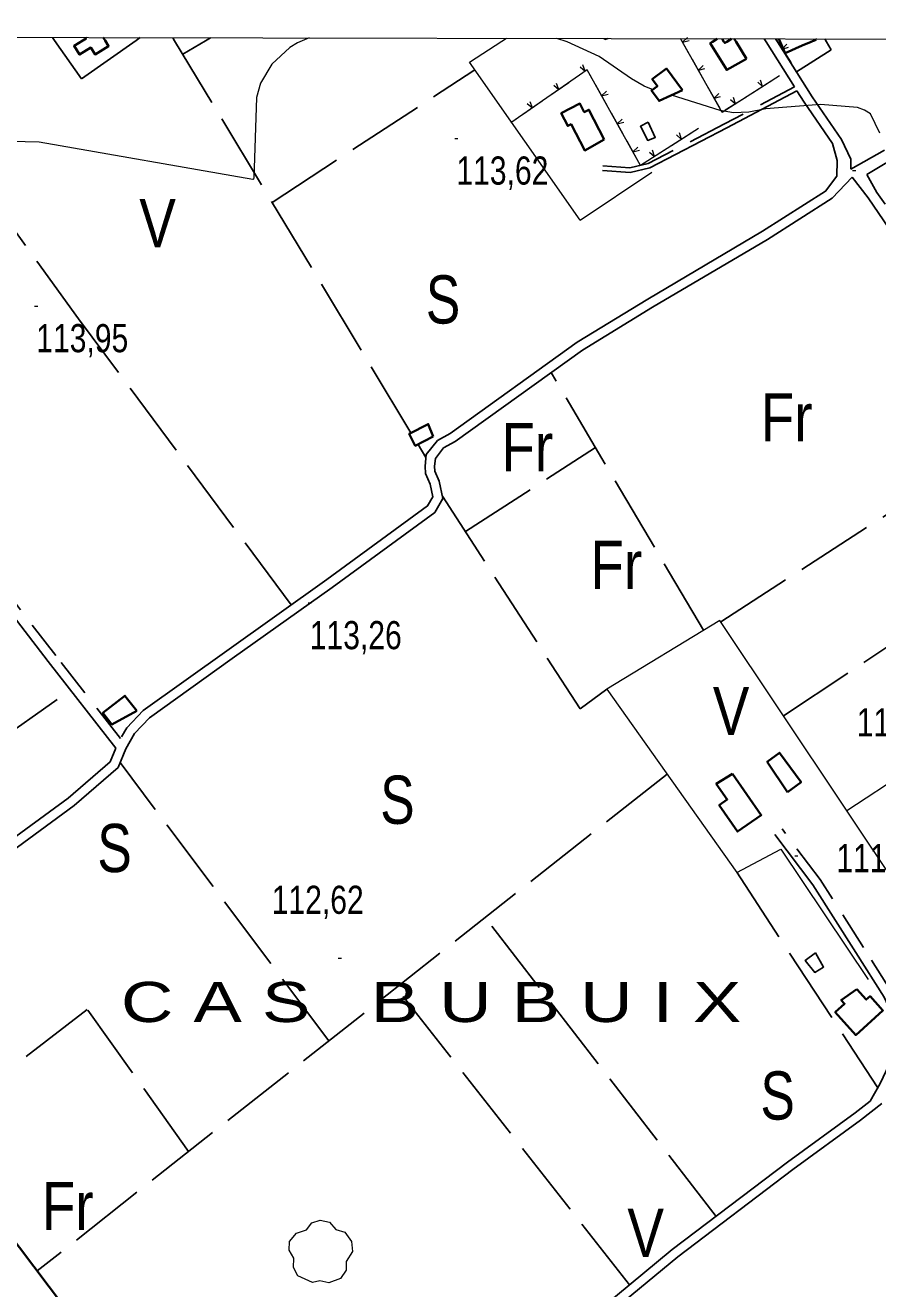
# Model space of a CAD drawing. Extents: x 483840 to 488445, y 4386047 to 4389027.
# Drawn here: x 486095.2 to 486360.3, y 4388367.4 to 4388760.3 of the extents above; entities that cross this region are included whole.
import ezdxf
from ezdxf.enums import TextEntityAlignment as Align

# ---------------------------------------------------------------- set-up
doc = ezdxf.new("R2010")
doc.units = 0
doc.header["$LTSCALE"] = 4
doc.linetypes.add('LONG_DASHED', pattern=[7.5, 6, -1.5])
doc.linetypes.add('MEDIUM_DASHED', pattern=[4.5, 3, -1.5])
for name, color, linetype, lineweight in [('1', 7, 'Continuous', 13), ('21', 7, 'Continuous', 25), ('24', 7, 'Continuous', 13), ('25', 7, 'LONG_DASHED', 25), ('29', 7, 'Continuous', 13), ('38', 7, 'Continuous', 25), ('47', 7, 'Continuous', 35), ('51', 7, 'Continuous', 13), ('6', 7, 'Continuous', 35), ('7', 7, 'Continuous', 13), ('9', 7, 'Continuous', 13)]:
    doc.layers.add(name, color=color, linetype=linetype, lineweight=lineweight)
doc.layers.add('31', color=7, linetype='Continuous')
doc.layers.add('5', color=7, linetype='Continuous')

msp = doc.modelspace()

# ---------------------------------------------------------------- linework, layer by layer
at = {"layer": '1'}
msp.add_lwpolyline([(484110.5, 4388760.3), (487685.8, 4388753.5), (487681.9, 4386441.2), (484105.5, 4386448.1)], close=True, dxfattribs=at)
at = {"layer": '21'}
for p, q in [((486275.39, 4388755.88), (486275.22, 4388756.18)), ((486276.32, 4388756.18), (486275.39, 4388755.88))]:
    msp.add_line(p, q, dxfattribs=at)
for points in [[(486288.93, 4388730.17), (486286.46, 4388728.89), (486288.79, 4388724.47), (486291.12, 4388725.45)], [(486340.97, 4388471.91), (486337.74, 4388469.5), (486340.68, 4388465.76), (486343.45, 4388467.41)]]:
    msp.add_lwpolyline(points, close=True, dxfattribs=at)
at = {"layer": '24'}
for p, q in [((486301.46, 4388751.78), (486299, 4388756.15)), ((486328.62, 4388756.09), (486333.35, 4388748.59)), ((486328.62, 4388756.09), (486332.62, 4388749.75)), ((486306.35, 4388743.08), (486302.68, 4388749.61)), ((486327.66, 4388743.22), (486321.32, 4388739.2)), ((486264.17, 4388742.44), (486258.01, 4388738.16)), ((486276.25, 4388735.11), (486272.59, 4388741.66)), ((486311.25, 4388734.37), (486307.58, 4388740.91)), ((486255.97, 4388736.74), (486249.81, 4388732.45)), ((486319.22, 4388737.86), (486312.89, 4388733.85)), ((486281.13, 4388726.39), (486277.47, 4388732.94)), ((486247.77, 4388731.03), (486246.23, 4388729.96)), ((486286, 4388717.67), (486282.34, 4388724.22)), ((486302.43, 4388726.85), (486296.11, 4388722.81)), ((486294.02, 4388721.47), (486287.7, 4388717.42))]:
    msp.add_line(p, q, dxfattribs=at)
for points in [[(486329.76, 4388744.55), (486311.9, 4388733.22), (486299, 4388756.15)], [(486301.1, 4388756.5), (486299.62, 4388755.05), (486301.62, 4388755.57)], [(486332.02, 4388754.44), (486330.62, 4388752.92), (486332.59, 4388753.54)], [(486267.71, 4388747.34), (486269.29, 4388746), (486268.59, 4388747.95)], [(486305.99, 4388747.8), (486304.52, 4388746.34), (486306.52, 4388746.86)], [(486304.53, 4388728.19), (486286.55, 4388716.69), (486269.92, 4388746.44), (486246.23, 4388729.96)], [(486271.38, 4388743.83), (486269.92, 4388746.44), (486266.21, 4388743.86)], [(486322.96, 4388742.61), (486324.49, 4388741.21), (486323.87, 4388743.18)], [(486259.51, 4388741.63), (486261.09, 4388740.3), (486260.38, 4388742.24)], [(486275.9, 4388739.83), (486274.42, 4388738.39), (486276.43, 4388738.9)], [(486310.89, 4388739.09), (486309.41, 4388737.64), (486311.42, 4388738.16)], [(486251.31, 4388735.93), (486252.89, 4388734.59), (486252.18, 4388736.54)], [(486314.53, 4388737.26), (486316.06, 4388735.86), (486315.43, 4388737.83)], [(486280.78, 4388731.11), (486279.3, 4388729.67), (486281.3, 4388730.18)], [(486297.74, 4388726.22), (486299.27, 4388724.83), (486298.64, 4388726.8)], [(486285.65, 4388722.39), (486284.17, 4388720.95), (486286.17, 4388721.46)], [(486289.32, 4388720.84), (486290.86, 4388719.45), (486290.23, 4388721.42)]]:
    msp.add_lwpolyline(points, dxfattribs=at)
at = {"layer": '25'}
for p, q in [((486104.3, 4388755.58), (486103.65, 4388756.51)), ((486130.94, 4388756.46), (486129.61, 4388755.53)), ((486141.59, 4388755.51), (486141.03, 4388756.44)), ((486215.13, 4388633.56), (486141.59, 4388755.51)), ((486151.24, 4388755.49), (486144.13, 4388751.31)), ((486152.8, 4388756.42), (486151.23, 4388755.49)), ((486343.86, 4388756.05), (486344.38, 4388755.11)), ((486171.92, 4388705.23), (486234.99, 4388746.46)), ((486063.66, 4388735.58), (486111.7, 4388669.05)), ((486177.83, 4388580.04), (486111.7, 4388669.05)), ((486306.1, 4388572.15), (486258.72, 4388652.3)), ((486311.46, 4388574.81), (486404.56, 4388634.97)), ((486219.77, 4388625.86), (486217.31, 4388629.94)), ((486232.03, 4388602.88), (486272.51, 4388628.99)), ((486330.99, 4388545.58), (486366.24, 4388568.94)), ((486011.75, 4388485.18), (486109.24, 4388553.5)), ((486189.6, 4388444.51), (486124.64, 4388531.01)), ((486294.77, 4388527.46), (486098.88, 4388372.95)), ((486316.44, 4388496.9), (486360.29, 4388429.87)), ((486310.02, 4388389.91), (486238.21, 4388482.85)), ((486283.12, 4388368.6), (486210.52, 4388461.01))]:
    msp.add_line(p, q, dxfattribs=at)
for points in [[(486129.62, 4388755.54), (486112.63, 4388743.69), (486104.29, 4388755.58)], [(486344.38, 4388755.12), (486345.76, 4388752.62), (486335.01, 4388745.77)], [(486224.92, 4388613.85), (486267.7, 4388547.78), (486276.02, 4388553.87)], [(486145.98, 4388410.1), (486114.45, 4388454.28), (486066.46, 4388417.1)]]:
    msp.add_lwpolyline(points, dxfattribs=at)
at = {"layer": '29'}
msp.add_lwpolyline([(486184.51, 4388369.3), (486179.97, 4388371.42), (486178.56, 4388373.96), (486178.66, 4388376.94), (486177.29, 4388379.35), (486177.33, 4388382.1), (486179.49, 4388384.7), (486182.68, 4388385.7), (486184.33, 4388387.89), (486186.9, 4388388.72), (486189.76, 4388388.07), (486191.71, 4388385.8), (486194.52, 4388384.98), (486196.65, 4388382.13), (486196.89, 4388379), (486195.01, 4388375.85), (486195.01, 4388373.17), (486193.19, 4388370.56), (486189.57, 4388369.22), (486186.8, 4388369.85)], close=True, dxfattribs=at)
at = {"layer": '38'}
for p, q in [((486325.59, 4388755.15), (486325, 4388756.09)), ((486334.4, 4388741.12), (486325.59, 4388755.16)), ((486329.11, 4388755.14), (486328.52, 4388756.08))]:
    msp.add_line(p, q, dxfattribs=at)
for points in [[(486351.95, 4388715.56), (486351.95, 4388718.62), (486349, 4388724.83), (486339.88, 4388738), (486329.11, 4388755.15)], [(486356.91, 4388713.91), (486390.65, 4388734.09), (486420.06, 4388754.97)], [(486125.14, 4388539.04), (486126.7, 4388541.81), (486131.81, 4388547.23), (486157.81, 4388565.81), (486188.91, 4388587.92), (486220.29, 4388610.84), (486221.92, 4388613.65), (486221.08, 4388617.59), (486219.65, 4388620.89), (486219.5, 4388623.24), (486219.87, 4388626.79), (486223.34, 4388631.17), (486227.31, 4388633.36), (486266.8, 4388661.78), (486288.77, 4388675.17), (486324.43, 4388696.23), (486344.05, 4388708.71), (486347.55, 4388713.33), (486347.69, 4388718.26), (486346.27, 4388723.56), (486337.4, 4388736.36), (486335.17, 4388739.91)], [(486335.17, 4388739.91), (486313.31, 4388728.36), (486289.38, 4388715.93), (486283.27, 4388714.48), (486274.69, 4388715.15)], [(486033.72, 4388459.48), (486052.43, 4388473.19), (486076.56, 4388492.95), (486110.38, 4388517.64), (486124.01, 4388529.51), (486126.45, 4388535.31), (486129.11, 4388540.04), (486133.77, 4388544.98), (486159.53, 4388563.39), (486190.65, 4388585.51), (486222.54, 4388608.81), (486225.06, 4388613.15), (486223.93, 4388618.5), (486222.58, 4388621.6), (486222.48, 4388623.18), (486222.74, 4388625.62), (486225.29, 4388628.86), (486228.9, 4388630.84), (486268.45, 4388659.3), (486290.29, 4388672.62), (486325.99, 4388693.7), (486346.1, 4388706.49), (486352.36, 4388713.1)], [(486438.94, 4388583.08), (486417.59, 4388614.59), (486380.14, 4388673.12), (486357.27, 4388706.61), (486352.36, 4388713.1)], [(486123.29, 4388535.46), (486102.27, 4388562.43), (486079.04, 4388592.63), (486059.8, 4388616.3), (486048.45, 4388632.26)], [(486031.88, 4388461.81), (486050.61, 4388475.53), (486074.74, 4388495.3), (486108.53, 4388519.96), (486121.54, 4388531.3), (486123.29, 4388535.46)], [(486368.72, 4388444.06), (486362.33, 4388458.05), (486353.45, 4388471.97), (486340.07, 4388493.03), (486328.26, 4388508.69)], [(486167.47, 4388276.64), (486196.77, 4388298.32), (486229.44, 4388324.85), (486265.99, 4388354.46), (486296.41, 4388379.57), (486332.22, 4388406.78), (486353.27, 4388422.12), (486357.92, 4388425.73), (486361.06, 4388431.21), (486363.9, 4388437.14), (486368.72, 4388444.06)], [(486169.13, 4388274.35), (486198.5, 4388296.09), (486231.22, 4388322.66), (486267.77, 4388352.28), (486298.16, 4388377.36), (486333.9, 4388404.52), (486354.96, 4388419.87), (486361.55, 4388424.99)]]:
    msp.add_lwpolyline(points, dxfattribs=at)
at = {"layer": '38', "linetype": 'MEDIUM_DASHED'}
for points in [[(486351.95, 4388715.56), (486389.06, 4388736.53), (486415.05, 4388754.98)], [(486334.4, 4388741.12), (486312.65, 4388729.62), (486288.88, 4388717.27), (486283.16, 4388715.92), (486274.8, 4388716.57)], [(486443.22, 4388581.34), (486420.29, 4388616.41), (486382.85, 4388674.91), (486360.04, 4388708.33), (486356.91, 4388713.91)], [(486124.76, 4388538.51), (486104.67, 4388564.29), (486081.42, 4388594.51), (486062.22, 4388618.14), (486050.92, 4388634.02)], [(486370.88, 4388446.75), (486364.82, 4388459.43), (486355.85, 4388473.5), (486342.41, 4388494.65), (486330.53, 4388510.4)]]:
    msp.add_lwpolyline(points, dxfattribs=at)
at = {"layer": '47'}
for p, q in [((486119.44, 4388756.48), (486120.01, 4388755.55)), ((486310.39, 4388756.12), (486308.88, 4388755.18)), ((486312.47, 4388755.18), (486311.89, 4388756.11)), ((486314.85, 4388756.11), (486313.33, 4388755.17)), ((486316.24, 4388755.17), (486315.66, 4388756.11)), ((486319.51, 4388749.88), (486316.24, 4388755.17)), ((486329.49, 4388756.08), (486329.92, 4388755.14)), ((486339.53, 4388755.12), (486341.1, 4388755.76)), ((486341.1, 4388755.76), (486340.96, 4388756.06))]:
    msp.add_line(p, q, dxfattribs=at)
for points in [[(486120.01, 4388755.55), (486121.08, 4388753.82), (486116.87, 4388751.22), (486115.54, 4388753.37), (486112.03, 4388751.2), (486110.36, 4388753.89), (486113.05, 4388755.57)], [(486113.04, 4388755.56), (486114.05, 4388756.19), (486113.86, 4388756.49)], [(486308.89, 4388755.19), (486308.18, 4388754.75), (486313.34, 4388746.4), (486319.51, 4388749.88)], [(486313.34, 4388755.18), (486312.71, 4388754.79), (486312.47, 4388755.18)], [(486329.91, 4388755.15), (486331.55, 4388751.6), (486336.8, 4388754.02), (486339.54, 4388755.13)]]:
    msp.add_lwpolyline(points, dxfattribs=at)
for points in [[(486299.57, 4388740.17), (486294.61, 4388746.83), (486290.17, 4388743.53), (486291.77, 4388741.37), (486289.93, 4388740.02), (486292.3, 4388736.77)], [(486275.21, 4388724.82), (486270.47, 4388734.04), (486269.04, 4388733.31), (486267.69, 4388735.94), (486261.86, 4388732.95), (486263.88, 4388729), (486264.92, 4388729.54), (486269.16, 4388721.36)], [(486222.03, 4388632.39), (486220.52, 4388636.29), (486214.56, 4388633.21), (486216.45, 4388629.54)], [(486129.83, 4388547.1), (486126.14, 4388551.82), (486119.3, 4388546.49), (486122.09, 4388542.9)], [(486332.26, 4388521.85), (486336.45, 4388524.94), (486329.7, 4388534.08), (486325.92, 4388531.3)], [(486315.14, 4388527.53), (486324.09, 4388514.71), (486316.72, 4388509.57), (486311.01, 4388517.75), (486313.51, 4388519.5), (486310.05, 4388524.43)], [(486353.81, 4388460.53), (486356.74, 4388457.31), (486357.92, 4388458.38), (486361.93, 4388453.95), (486353.46, 4388446.3), (486347.06, 4388453.38), (486349.99, 4388456.03), (486348.93, 4388457.19)]]:
    msp.add_lwpolyline(points, close=True, dxfattribs=at)
at = {"layer": '51'}
for p, q in [((486243.38, 4388755.31), (486244.83, 4388756.24)), ((486267.75, 4388699.68), (486290.08, 4388714.57)), ((486350.66, 4388516.14), (486442.59, 4388576.42))]:
    msp.add_line(p, q, dxfattribs=at)
for points in [[(486267.75, 4388699.68), (486233.32, 4388748.83), (486243.39, 4388755.32)], [(486387.72, 4388460.66), (486311.17, 4388575.23), (486276.02, 4388553.87), (486316.47, 4388496.85), (486330.19, 4388504.07), (486357.33, 4388463.53)]]:
    msp.add_lwpolyline(points, dxfattribs=at)
at = {"layer": '6'}
msp.add_lwpolyline([(486041.26, 4388448.96), (486070.33, 4388412.2), (486088.62, 4388386.55), (486116.6, 4388349.44), (486140.39, 4388314.86), (486164.8, 4388280.35), (486169.29, 4388274.24)], dxfattribs=at)
at = {"layer": '7'}
for p, q in [((486228.73, 4388725.12), (486229.73, 4388725.12)), ((486352.44, 4388715.12), (486353.44, 4388715.12)), ((486098.07, 4388673), (486099.07, 4388673)), ((486183.13, 4388580.65), (486184.13, 4388580.65)), ((486334.49, 4388501.98), (486335.49, 4388501.98)), ((486192.47, 4388470.17), (486193.47, 4388470.17))]:
    msp.add_line(p, q, dxfattribs=at)
at = {"layer": '9'}
for points in [[(486183.42, 4388756.36), (486179.83, 4388754.85), (486177.45, 4388753.41), (486171.84, 4388748.22), (486168.33, 4388742.34), (486167.13, 4388737.89), (486166.27, 4388712.73), (486166.19, 4388712.57), (486166.15, 4388712.52), (486166.11, 4388712.48), (486165.89, 4388712.35), (486099.53, 4388723.97), (486090.75, 4388724.18)], [(486290.39, 4388740.36), (486289.39, 4388740.67), (486287.63, 4388741.41), (486283.74, 4388743.62), (486273.61, 4388750.62), (486263.7, 4388755.2), (486260.51, 4388756.21)], [(486325.54, 4388734.34), (486320.22, 4388733.29), (486315.41, 4388733.11), (486311.3, 4388733.82), (486296.13, 4388738.56)], [(486360.98, 4388726.74), (486358.02, 4388732.81), (486356.23, 4388733.91), (486354.01, 4388734.75), (486342.47, 4388735.67), (486325.54, 4388734.34)]]:
    msp.add_lwpolyline(points, dxfattribs=at)

# ---------------------------------------------------------------- texts
at = {"layer": '31'}
for s, width, p in [('V', 0.85, (486136.31, 4388691.24)), ('S', 0.8, (486225.1, 4388667.54)), ('Fr', 0.85, (486331.98, 4388630.88)), ('Fr', 0.85, (486251.28, 4388621.64)), ('Fr', 0.85, (486279.01, 4388584.98)), ('V', 0.85, (486314.68, 4388539.55)), ('S', 0.8, (486210.91, 4388511.97)), ('S', 0.8, (486122.93, 4388496.96)), ('S', 0.8, (486329.17, 4388420)), ('Fr', 0.85, (486108.37, 4388385.64)), ('V', 0.85, (486288.12, 4388377.26))]:
    msp.add_text(s, height=15, dxfattribs=dict(at, width=width)).set_placement(p, align=Align.CENTER)
at = {"layer": '5', "width": 1.35}
msp.add_text('C A S   B U B U I X', height=12.49, dxfattribs=at).set_placement((486317.88, 4388450.34), align=Align.RIGHT)
at = {"layer": '7', "width": 0.8}
for s, p in [('113,62', (486229.23, 4388710.75)), ('113,95', (486098.57, 4388658.63)), ('113,26', (486183.63, 4388566.28)), ('111,64', (486353.76, 4388539.18)), ('111,62', (486347.42, 4388496.93)), ('112,62', (486171.79, 4388483.98))]:
    msp.add_text(s, height=8.75, dxfattribs=at).set_placement(p)

doc.saveas('drawing.dxf')
